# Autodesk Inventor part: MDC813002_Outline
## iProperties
Shininess: 64.0
Length Units: 11272
Angle Units: 11279
Time Units: 11290
Mass Units: 11286
Length Display Precision: 3
Angle Display Precision: 2
Compacted: True
Part Number: MDC813002_Outline
Document SubType Name: Modeling
Created: 2004-07
Designer: John Blackburn
Manufacturer: Standard
Standards Organization: Custom
Density: 0.0
Volumn: 0.0
Area: 0.0
PropertySet Name: Model Information
Control State: 0
Master: False
Checked Out: False
Author: John Blackburn
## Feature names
1. Extrusion1
2. Extrusion3
